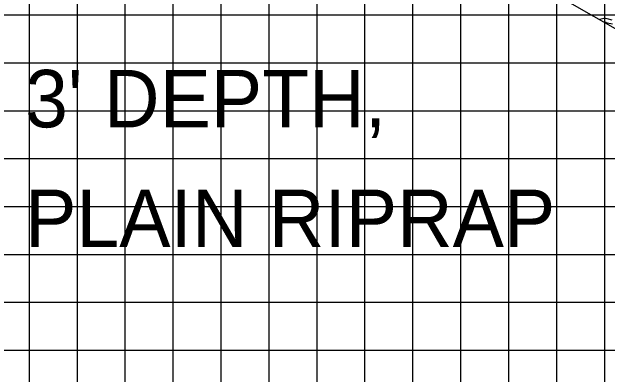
# Model space of a CAD drawing. Extents: x 1769661 to 1770005, y 442591 to 442811.
# Drawn here: x 1769728.65 to 1769741.07, y 442707.17 to 442714.73 of the extents above; entities that cross this region are included whole.
import ezdxf

# ---------------------------------------------------------------- set-up
doc = ezdxf.new("R2010")
doc.units = 0
for name, color, linetype in [('ANNOTATION', 7, 'Continuous'), ('D_Text_Standard', 7, 'Continuous'), ('GRUBBING IN FILL', 7, 'Continuous'), ('MAJOR', 7, 'Continuous'), ('MINOR', 7, 'Continuous')]:
    doc.layers.add(name, color=color, linetype=linetype)

msp = doc.modelspace()

# ---------------------------------------------------------------- linework, layer by layer
at = {"layer": 'ANNOTATION'}
msp.add_lwpolyline([(1769791.352, 442685.747), (1769732.818, 442719.196), (1769731.806, 442719.702), (1769730.917, 442720.017), (1769730.071, 442720.196), (1769729.233, 442720.252)], dxfattribs=at)
at = {"layer": 'GRUBBING IN FILL'}
for p, q in [((1769740.994, 442714.594), (1769740.912, 442714.571)), ((1769741.065, 442714.585), (1769741.031, 442714.594)), ((1769741.173, 442714.554), (1769741.065, 442714.585)), ((1769741.045, 442714.506), (1769741.065, 442714.502)), ((1769741.065, 442714.502), (1769741.181, 442714.482))]:
    msp.add_line(p, q, dxfattribs=at)
for centre, start_param, end_param in [((1769741.013, 442714.529), 6.004886, 6.561485), ((1769741.034, 442714.439), 6.110994, 6.417783)]:
    msp.add_ellipse(centre, major_axis=(0, 0.0683), ratio=0.99895, start_param=start_param, end_param=end_param, dxfattribs=at)
at = {"layer": 'MAJOR'}
for p, q in [((1769737.015, 442678.665), (1769737.015, 442733.665)), ((1769687.015, 442713.665), (1769967.015, 442713.665)), ((1769687.015, 442708.665), (1769967.015, 442708.665))]:
    msp.add_line(p, q, dxfattribs=at)
at = {"layer": 'MINOR'}
for p, q in [((1769729.015, 442678.665), (1769729.015, 442733.665)), ((1769730.015, 442678.665), (1769730.015, 442733.665)), ((1769731.015, 442678.665), (1769731.015, 442733.665)), ((1769732.015, 442678.665), (1769732.015, 442733.665)), ((1769733.015, 442678.665), (1769733.015, 442733.665)), ((1769734.015, 442678.665), (1769734.015, 442733.665)), ((1769735.015, 442678.665), (1769735.015, 442733.665)), ((1769736.015, 442678.665), (1769736.015, 442733.665)), ((1769738.015, 442678.665), (1769738.015, 442733.665)), ((1769739.015, 442678.665), (1769739.015, 442733.665)), ((1769740.015, 442678.665), (1769740.015, 442733.665)), ((1769741.015, 442678.665), (1769741.015, 442733.665)), ((1769687.015, 442714.665), (1769967.015, 442714.665)), ((1769687.015, 442712.665), (1769967.015, 442712.665)), ((1769687.015, 442711.665), (1769967.015, 442711.665)), ((1769687.015, 442710.665), (1769967.015, 442710.665)), ((1769687.015, 442709.665), (1769967.015, 442709.665)), ((1769687.015, 442707.665), (1769967.015, 442707.665))]:
    msp.add_line(p, q, dxfattribs=at)

# ---------------------------------------------------------------- texts
at = {"layer": 'D_Text_Standard'}
for s, p in [("3' DEPTH, ", (1769728.926, 442712.318)), ('PLAIN RIPRAP', (1769728.926, 442709.818))]:
    msp.add_text(s, height=1.2, dxfattribs=at).set_placement(p)

doc.saveas('drawing.dxf')
